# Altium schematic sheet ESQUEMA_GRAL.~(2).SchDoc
size A4
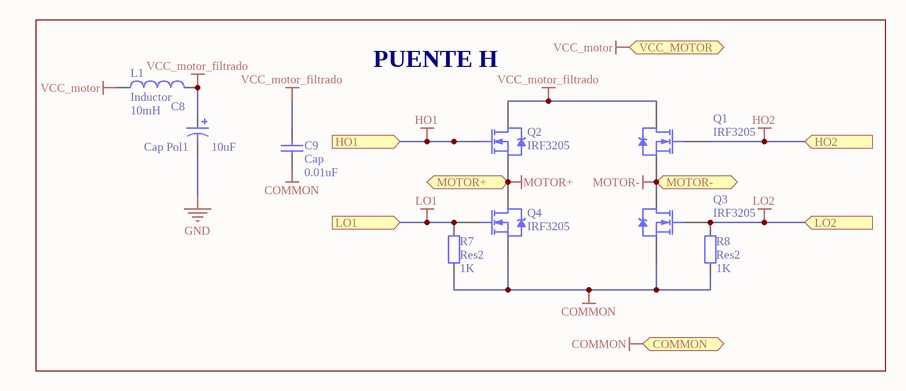
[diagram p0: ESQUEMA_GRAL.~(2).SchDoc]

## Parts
C8  Cap Pol1  value 10uF  [CAPPR5-13X16]
C9  Cap  value 0.01uF  [RAD-0.2]
L1  Inductor  value 10mH  [bobina_Choque]
Q1  IRF3205  [TO-220AB]
Q2  IRF3205  [TO-220AB]
Q3  IRF3205  [TO-220AB]
Q4  IRF3205  [TO-220AB]
R7  Res2  value 1K  [AXIAL-0.3]
R8  Res2  value 1K  [AXIAL-0.3]

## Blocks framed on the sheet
PUENTE H: C8 C9 L1 Q1-Q4 R7 R8

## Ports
COMMON (out), HO1 (in), HO2 (in), LO1 (in), LO2 (in), MOTOR+ (bidir), MOTOR- (bidir), VCC_MOTOR (in)

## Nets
COMMON: C9.1 Q3.3(S) Q4.3(S) R7.1 R8.1 ; port COMMON
GND: C8.2
HO1: Q2.1(G) ; port HO1
HO2: Q1.1(G) ; port HO2
LO1: Q4.1(G) R7.2 ; port LO1
LO2: Q3.1(G) R8.2 ; port LO2
MOTOR+: Q2.3(S) Q4.2(D) ; port MOTOR+
MOTOR-: Q1.3(S) Q3.2(D) ; port MOTOR-
VCC_motor: L1.1 ; port VCC_MOTOR
VCC_motor_filtrado: C8.1 C9.2 L1.2 Q1.2(D) Q2.2(D)

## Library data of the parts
C8 = Cap Pol1: Polarized Capacitor (Radial)
C9 = Cap: Capacitor
L1 = Inductor: Code_IEC: 1005
Q1-Q4 = IRF3205: HEXFET Power MOSFET; Note: Pin 2 is electrically connected to pin 4.
R7 R8 = Res2: Resistor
